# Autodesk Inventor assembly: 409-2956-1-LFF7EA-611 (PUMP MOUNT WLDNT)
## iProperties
Created: 2010-06
Part Number: 409-2956-1-LFF7EA-611 (PUMP MOUNT WLDNT)
Document SubType Name: Weldment
Designer: S. Boerckel
Weld Material: Welded Aluminum-6061
Mass: 197223 g
Surface Area: 33949.3 cm^2
Volume: 25092 cm^3
Density: 7.86 g/cm^3
Description: PUMP MOUNT
Material: WELDMENT
SMR: =<Material>
Author: S. Boerckel
Revision Number: 0
Subject: LIQUID FUEL FORWARDING PUMP SKID-7EA
